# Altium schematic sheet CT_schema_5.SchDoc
size 316 x 185 mm
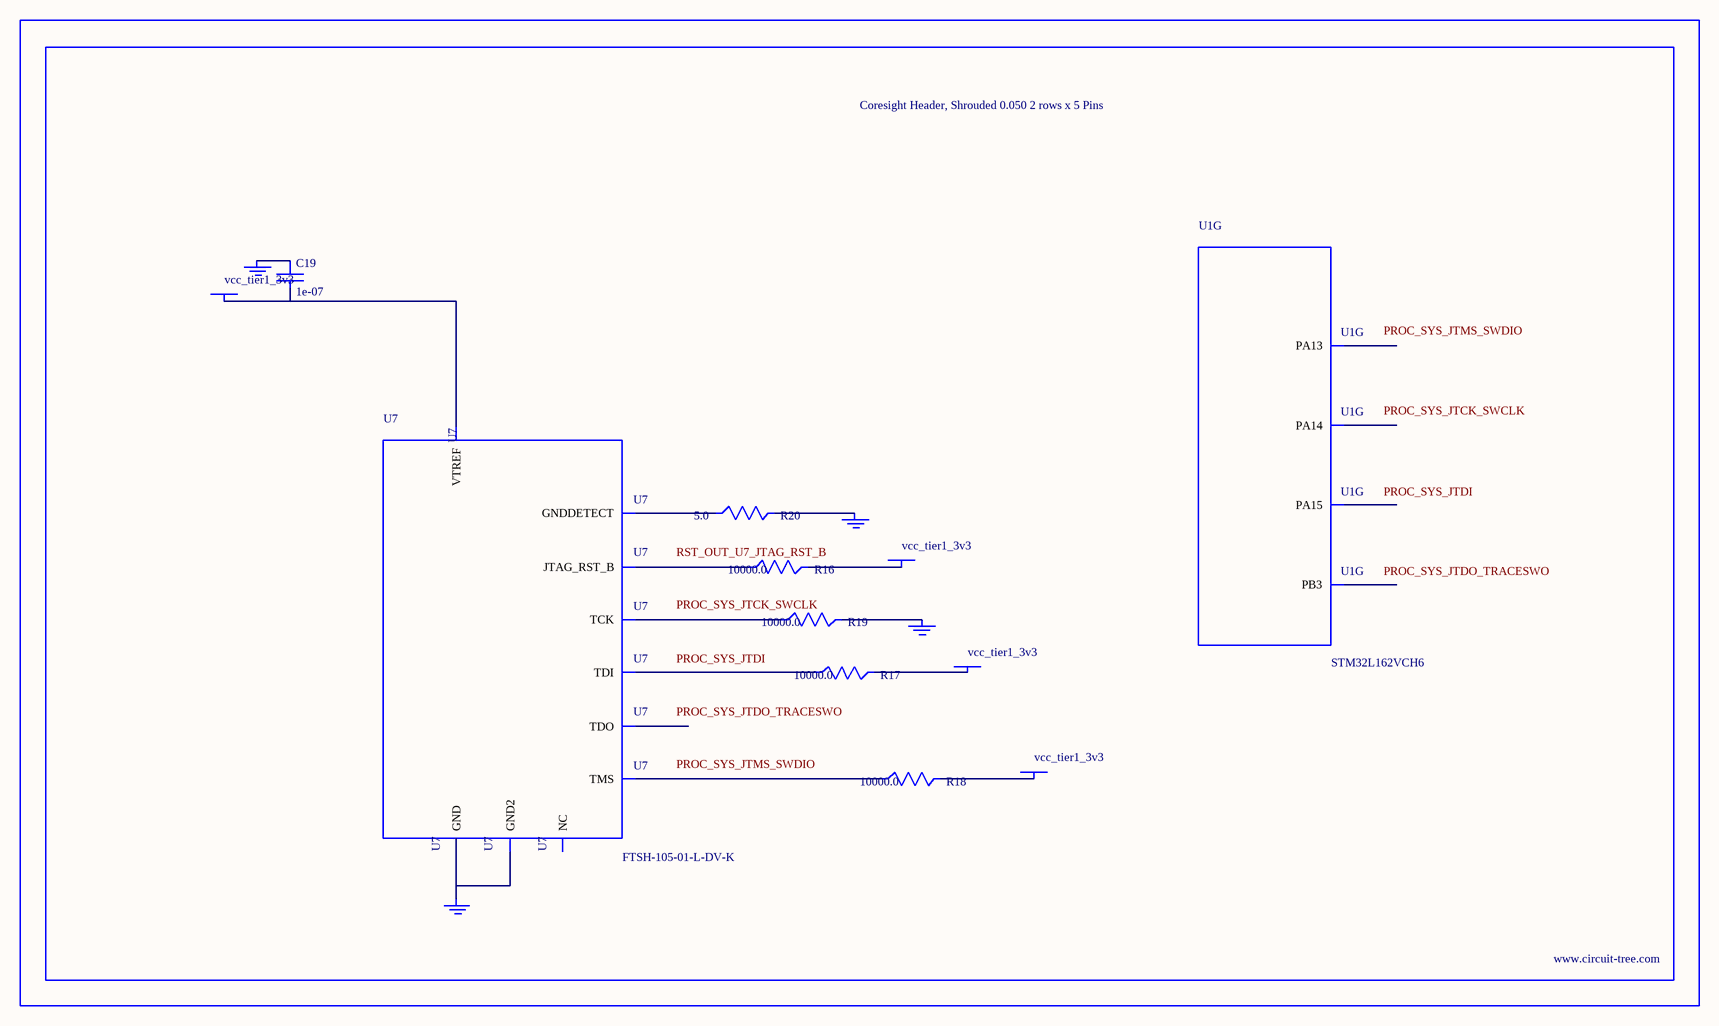
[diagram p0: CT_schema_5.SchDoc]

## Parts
BORDER4  (no value)
C19  1e-07  [C0402]
GND_INSTANCE_4_0  (no value)
GND_INSTANCE_4_1  (no value)
GND_INSTANCE_4_2  (no value)
GND_INSTANCE_4_3  (no value)
POWER_INSTANCE_4_0  vcc_tier1_3v3
POWER_INSTANCE_4_1  vcc_tier1_3v3
POWER_INSTANCE_4_2  vcc_tier1_3v3
POWER_INSTANCE_4_3  vcc_tier1_3v3
R16  10000.0  [R0603]
R17  10000.0  [R0603]
R18  10000.0  [R0603]
R19  10000.0  [R0603]
R20  5.0  [R0603]
U1  STM32L162VCH6  [UFBGA100]  (part G of 9)
U7  FTSH-105-01-L-DV-K  [SAMTEC_FTSH-105-01-L-DV-K]

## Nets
NetC19_1: C19.1 GND_INSTANCE_4_0.0(GND)
NetC19_2: C19.2 POWER_INSTANCE_4_0.0(PWR) U7.1(VTREF)
NetGND_INSTANCE_4_1_0: GND_INSTANCE_4_1.0(GND) R19.2
NetGND_INSTANCE_4_2_0: GND_INSTANCE_4_2.0(GND) R20.2
NetGND_INSTANCE_4_3_0: GND_INSTANCE_4_3.0(GND) U7.3(GND) U7.5(GND2)
NetPOWER_INSTANCE_4_1_0: POWER_INSTANCE_4_1.0(PWR) R18.2
NetPOWER_INSTANCE_4_2_0: POWER_INSTANCE_4_2.0(PWR) R17.2
NetPOWER_INSTANCE_4_3_0: POWER_INSTANCE_4_3.0(PWR) R16.2
NetR16_1: R16.1 U7.10(JTAG_RST_B)
NetR17_1: R17.1 U7.8(TDI)
NetR18_1: R18.1 U7.2(TMS)
NetR19_1: R19.1 U7.4(TCK)
NetR20_1: R20.1 U7.9(GNDDETECT)

Not connected (* = marked no-connect by the designer): U1 A8(PB3) A9(PA15) A10(PA14) A11(PA13); U7 6(TDO) 7(NC)

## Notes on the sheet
- Labels drawn without touching a wire or pin: PROC_SYS_JTCK_SWCLK, PROC_SYS_JTDI, PROC_SYS_JTDO_TRACESWO, PROC_SYS_JTMS_SWDIO, RST_OUT_U7_JTAG_RST_B

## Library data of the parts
BORDER4 = BORDER_PAGE4
C19 = C0402C104K3RACTU
GND_INSTANCE_4_0-GND_INSTANCE_4_3 = GND
POWER_INSTANCE_4_0-POWER_INSTANCE_4_3 = PWR
R16-R19 = RC0603JR-0710KL
R20 = ERJ-3GEYJ5R1V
